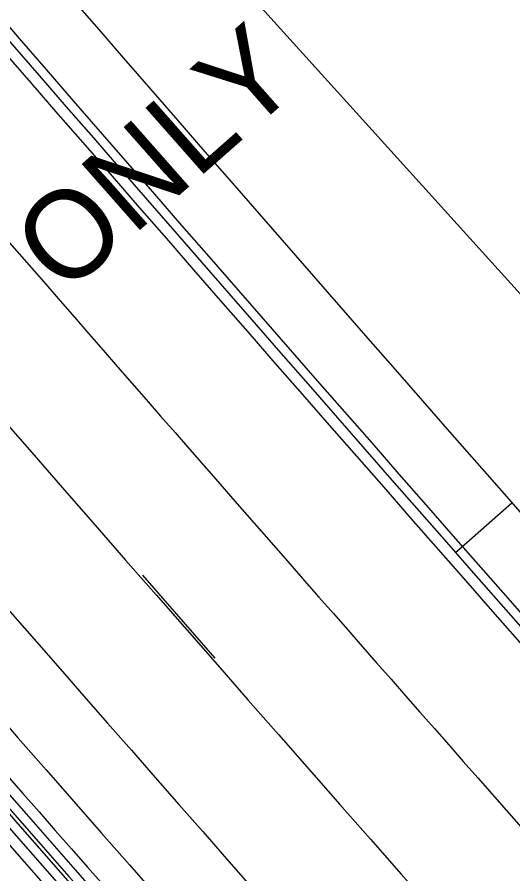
# Model space of a CAD drawing. Extents: x 2252205 to 2259955, y 13788514 to 13798103.
# Drawn here: x 2256494.6 to 2256539.6, y 13792111.5 to 13792189.4 of the extents above; entities that cross this region are included whole.
import ezdxf

# ---------------------------------------------------------------- set-up
doc = ezdxf.new("R2010")
doc.units = 0
for name, color, linetype in [('GEOM_CENTERLINE_ALIGN', 7, 'Continuous'), ('ROAD_BIKE_SHARED_USE', 7, 'Continuous'), ('Road_Curb_Back', 7, 'Continuous'), ('Road_Curb_Face', 7, 'Continuous'), ('ROAD_DRIVEWAY_EP', 7, 'Continuous'), ('Road_EdgeOfPavementInside', 7, 'Continuous'), ('Road_EdgeOfPavementOutside', 7, 'Continuous'), ('ROAD_ROW_EXIST', 7, 'Continuous'), ('ROAD_ROW_PROPOSED', 7, 'Continuous'), ('Road_Sidewalk_Back', 7, 'Continuous'), ('TRAF_PAVMRK_W_4IN_BRK', 7, 'Continuous'), ('TRAF_PAVMRK_W_4IN_SLD', 7, 'Continuous'), ('TRAF_PAVMRK_W_8IN_SLD', 7, 'Continuous'), ('TRAF_PAVMRK_W_RT_TRN_ARROW_WORD', 7, 'Continuous'), ('TRAF_PAVMRK_Y_4IN_SLD', 7, 'Continuous')]:
    doc.layers.add(name, color=color, linetype=linetype)

msp = doc.modelspace()

# ---------------------------------------------------------------- linework, layer by layer
at = {"layer": 'GEOM_CENTERLINE_ALIGN'}
msp.add_arc((2265118.999, 13799669.27), 11459.16, 219.4185534, 224.3273853, dxfattribs=at)
at = {"layer": 'ROAD_BIKE_SHARED_USE'}
for radius, start, end in [(11494.993, 220.9250736, 223.155573), (11504.993, 220.9281736, 223.1564697)]:
    msp.add_arc((2265118.999, 13799669.27), radius, start, end, dxfattribs=at)
at = {"layer": 'Road_Curb_Back'}
for radius, start, end in [(11417.327, 220.7168327, 221.9218682), (11464.327, 220.6217644, 222.2961287), (11463.993, 220.6217644, 222.072794), (11489.993, 220.9232633, 223.1551241)]:
    msp.add_arc((2265118.999, 13799669.27), radius, start, end, dxfattribs=at)
at = {"layer": 'Road_Curb_Face'}
for radius, start, end in [(11418.16, 220.7168327, 221.9218682), (11489.16, 220.9232633, 223.1550492)]:
    msp.add_arc((2265118.999, 13799669.27), radius, start, end, dxfattribs=at)
at = {"layer": 'ROAD_DRIVEWAY_EP'}
msp.add_line((2256539.544, 13792145.188), (2256534.419, 13792140.667), dxfattribs=at)
at = {"layer": 'Road_EdgeOfPavementInside'}
for radius, end in [(11463.16, 222.0719881), (11465.16, 222.2969334)]:
    msp.add_arc((2265118.999, 13799669.27), radius, 220.6217644, end, dxfattribs=at)
at = {"layer": 'Road_EdgeOfPavementOutside'}
for radius, start, end in [(11418.16, 220.7168327, 221.9218682), (11489.16, 220.9232633, 223.1550492)]:
    msp.add_arc((2265118.999, 13799669.27), radius, start, end, dxfattribs=at)
at = {"layer": 'ROAD_ROW_EXIST'}
msp.add_line((2256429.728, 13792286.644), (2256802.399, 13791873.964), dxfattribs=at)
msp.add_arc((2265124.02, 13799672.913), 11509.2, 220.7607024, 223.0233974, dxfattribs=at)
at = {"layer": 'ROAD_ROW_PROPOSED'}
msp.add_arc((2265116.027, 13799666.586), 11519.16, 220.6777899, 223.1584667, dxfattribs=at)
at = {"layer": 'Road_Sidewalk_Back'}
msp.add_arc((2265118.999, 13799669.27), 11411.327, 220.7168327, 221.9236801, dxfattribs=at)
at = {"layer": 'TRAF_PAVMRK_W_4IN_BRK'}
for points in [[(2256512.564, 13792131.097), (2256505.997, 13792138.639)], [(2256512.571, 13792131.09), (2256512.564, 13792131.097)]]:
    msp.add_lwpolyline(points, dxfattribs=at)
msp.add_arc((2265118.999, 13799669.27), 11441.16, 220.6468312, 223.3512093, dxfattribs=at)
at = {"layer": 'TRAF_PAVMRK_W_4IN_SLD'}
for radius, start, end in [(11419.16, 220.7168327, 221.9218682), (11488.16, 220.9232633, 223.3354344)]:
    msp.add_arc((2265118.999, 13799669.27), radius, start, end, dxfattribs=at)
at = {"layer": 'TRAF_PAVMRK_W_8IN_SLD'}
for radius, start, end in [(11430.16, 220.6468601, 221.9218682), (11452.16, 220.6468024, 221.6963939)]:
    msp.add_arc((2265118.999, 13799669.27), radius, start, end, dxfattribs=at)
at = {"layer": 'TRAF_PAVMRK_Y_4IN_SLD'}
for radius, start, end in [(11466.16, 220.621747, 223.3428022), (11462.16, 220.6467762, 222.0710209)]:
    msp.add_arc((2265118.999, 13799669.27), radius, start, end, dxfattribs=at)

# ---------------------------------------------------------------- texts
at = {"layer": 'TRAF_PAVMRK_W_RT_TRN_ARROW_WORD'}
msp.add_text('ONLY', height=8, rotation=41.41182, dxfattribs=at).set_placement((2256498.839, 13792163.94))

doc.saveas('drawing.dxf')
